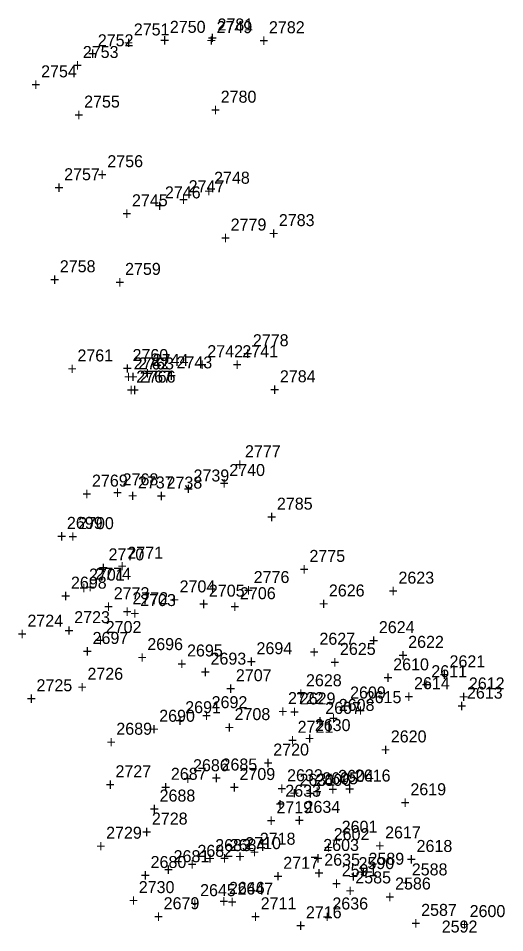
# Model space of a CAD drawing. Extents: x 2192192 to 2193475, y 863716 to 864270.
# Drawn here: x 2192604 to 2192705.3, y 864079.2 to 864269.6 of the extents above; entities that cross this region are included whole.
import ezdxf

# ---------------------------------------------------------------- set-up
doc = ezdxf.new("R2010")
doc.units = 0
for name, color, linetype in [('S_Drainage_Waterway', 7, 'Continuous'), ('S_Ground_Elevation', 7, 'Continuous'), ('S_Ground_SpotElevation', 7, 'Continuous')]:
    doc.layers.add(name, color=color, linetype=linetype)

msp = doc.modelspace()

# ---------------------------------------------------------------- texts
at = {"layer": 'S_Drainage_Waterway'}
for s, p in [('2749', (2192645.32, 864266.53)), ('2752', (2192620.58, 864263.79)), ('+', (2192643.26, 864263.78)), ('+', (2192618.52, 864261.04)), ('2748', (2192644.8, 864235.16)), ('+', (2192642.74, 864232.41)), ('2745', (2192627.7, 864230.46)), ('+', (2192625.64, 864227.71)), ('2741', (2192650.69, 864199.02)), ('2744', (2192632.03, 864197.22)), ('+', (2192648.63, 864196.27)), ('+', (2192629.97, 864194.47)), ('2740', (2192647.97, 864174.28)), ('2737', (2192628.94, 864171.69)), ('+', (2192645.91, 864171.53)), ('+', (2192626.88, 864168.94)), ('2699', (2192614.15, 864163.27)), ('2700', (2192616.48, 864163.21)), ('+', (2192612.08, 864160.52)), ('+', (2192614.42, 864160.46)), ('2698', (2192614.99, 864150.82)), ('2701', (2192618.75, 864152.5)), ('2623', (2192683.2, 864151.86)), ('+', (2192616.69, 864149.75)), ('2626', (2192668.71, 864149.19)), ('+', (2192612.92, 864148.07)), ('2703', (2192629.4, 864147.19)), ('2706', (2192650.2, 864148.62)), ('+', (2192681.14, 864149.11)), ('+', (2192648.14, 864145.87)), ('+', (2192666.65, 864146.44)), ('+', (2192627.33, 864144.44)), ('2702', (2192622.23, 864141.58)), ('2697', (2192619.49, 864139.3)), ('+', (2192620.17, 864138.83)), ('2622', (2192685.23, 864138.49)), ('+', (2192617.43, 864136.55)), ('2694', (2192653.64, 864137.16)), ('2693', (2192644.06, 864134.99)), ('+', (2192651.58, 864134.41)), ('2610', (2192682.11, 864133.8)), ('+', (2192683.17, 864135.74)), ('2621', (2192693.84, 864134.43)), ('+', (2192642, 864132.24)), ('2611', (2192690.05, 864132.37)), ('+', (2192680.05, 864131.05)), ('+', (2192691.78, 864131.68)), ('2612', (2192697.87, 864129.82)), ('2609', (2192673.13, 864127.93)), ('+', (2192687.99, 864129.62)), ('2629', (2192662.65, 864126.69)), ('+', (2192695.81, 864127.07)), ('2692', (2192644.29, 864125.92)), ('+', (2192671.07, 864125.18)), ('+', (2192642.23, 864123.17)), ('+', (2192660.58, 864123.94)), ('2689', (2192624.44, 864120.39)), ('2630', (2192665.78, 864121.15)), ('+', (2192622.38, 864117.64)), ('+', (2192663.72, 864118.4)), ('2685', (2192646.35, 864112.94)), ('+', (2192644.29, 864110.19)), ('2632', (2192660, 864110.7)), ('2631', (2192662.59, 864109.76)), ('2604', (2192670.63, 864110.57)), ('+', (2192657.93, 864107.95)), ('2633', (2192659.63, 864107.48)), ('+', (2192668.57, 864107.82)), ('2688', (2192633.45, 864106.47)), ('+', (2192660.53, 864107.01)), ('+', (2192631.39, 864103.72)), ('+', (2192657.57, 864104.73)), ('2634', (2192663.64, 864104.11)), ('+', (2192661.58, 864101.36)), ('2601', (2192671.38, 864099.98)), ('2684', (2192648.05, 864096.17)), ('+', (2192669.32, 864097.23)), ('2681', (2192636.37, 864093.84)), ('2680', (2192631.58, 864092.63)), ('+', (2192645.99, 864093.42)), ('2635', (2192667.75, 864093.11)), ('2589', (2192676.96, 864093.31)), ('+', (2192634.31, 864091.09)), ('+', (2192665.68, 864090.36)), ('+', (2192674.9, 864090.56)), ('2588', (2192685.98, 864091.09)), ('+', (2192629.51, 864089.88)), ('+', (2192683.91, 864088.34)), ('2647', (2192649.66, 864087.1)), ('2679', (2192634.3, 864084.04)), ('+', (2192647.59, 864084.35)), ('2636', (2192669.44, 864083.99)), ('2587', (2192687.93, 864082.66)), ('+', (2192632.23, 864081.29)), ('+', (2192667.37, 864081.24)), ('+', (2192685.86, 864079.91))]:
    msp.add_text(s, height=2.5, dxfattribs=at).set_placement(p)
at = {"layer": 'S_Ground_Elevation'}
for s, p in [('2781', (2192645.51, 864267.08)), ('2782', (2192656.23, 864266.51)), ('+', (2192643.45, 864264.33)), ('+', (2192654.17, 864263.76)), ('2753', (2192617.46, 864261.35)), ('+', (2192615.39, 864258.6)), ('2754', (2192608.77, 864257.32)), ('+', (2192606.71, 864254.57)), ('2780', (2192646.18, 864252.04)), ('2755', (2192617.73, 864251.02)), ('+', (2192644.12, 864249.29)), ('+', (2192615.67, 864248.27)), ('2756', (2192622.57, 864238.6)), ('2757', (2192613.57, 864235.89)), ('+', (2192620.51, 864235.85)), ('+', (2192611.51, 864233.14)), ('2779', (2192648.26, 864225.41)), ('2783', (2192658.29, 864226.33)), ('+', (2192656.23, 864223.58)), ('+', (2192646.2, 864222.66)), ('2758', (2192612.67, 864216.72)), ('2759', (2192626.26, 864216.17)), ('+', (2192610.61, 864213.97)), ('+', (2192624.2, 864213.42)), ('2778', (2192652.88, 864201.31)), ('2761', (2192616.34, 864198.15)), ('2760', (2192627.81, 864198.23)), ('2762', (2192628.05, 864196.48)), ('2763', (2192629.01, 864196.48)), ('+', (2192650.82, 864198.56)), ('+', (2192614.28, 864195.4)), ('+', (2192625.75, 864195.48)), ('+', (2192625.99, 864193.73)), ('+', (2192626.95, 864193.73)), ('2767', (2192628.6, 864193.74)), ('2766', (2192629.33, 864193.73)), ('2784', (2192658.51, 864193.8)), ('+', (2192626.54, 864190.99)), ('+', (2192627.27, 864190.98)), ('+', (2192656.45, 864191.05)), ('2777', (2192651.24, 864178.19)), ('+', (2192649.18, 864175.44)), ('2769', (2192619.37, 864172.07)), ('2768', (2192625.75, 864172.34)), ('+', (2192617.31, 864169.32)), ('+', (2192623.69, 864169.59)), ('2785', (2192657.89, 864167.27)), ('+', (2192655.83, 864164.52)), ('2770', (2192622.82, 864156.71)), ('2771', (2192626.74, 864157.05)), ('2775', (2192664.66, 864156.39)), ('2774', (2192620.07, 864152.67)), ('+', (2192620.76, 864153.96)), ('+', (2192624.68, 864154.3)), ('+', (2192662.6, 864153.64)), ('2776', (2192653.05, 864151.99)), ('+', (2192618.01, 864149.92)), ('2773', (2192623.9, 864148.62)), ('2772', (2192627.79, 864147.58)), ('+', (2192650.99, 864149.24)), ('+', (2192621.84, 864145.87)), ('2723', (2192615.67, 864143.63)), ('+', (2192625.73, 864144.83)), ('2724', (2192605.92, 864142.9)), ('+', (2192603.86, 864140.15)), ('+', (2192613.61, 864140.88)), ('2726', (2192618.42, 864131.84)), ('2707', (2192649.34, 864131.53)), ('2614', (2192686.45, 864129.88)), ('2725', (2192607.82, 864129.45)), ('+', (2192616.36, 864129.09)), ('+', (2192647.28, 864128.78)), ('2613', (2192697.47, 864127.9)), ('+', (2192605.76, 864126.7)), ('2722', (2192660.2, 864126.78)), ('2615', (2192676.39, 864126.97)), ('+', (2192684.38, 864127.13)), ('+', (2192695.41, 864125.15)), ('2708', (2192649.07, 864123.44)), ('+', (2192658.14, 864124.03)), ('+', (2192674.33, 864124.22)), ('2721', (2192662.2, 864120.79)), ('+', (2192647.01, 864120.69)), ('+', (2192660.14, 864118.04)), ('2720', (2192657.13, 864116.05)), ('+', (2192655.07, 864113.3)), ('2727', (2192624.26, 864111.53)), ('2709', (2192650.09, 864110.96)), ('2616', (2192674.12, 864110.64)), ('+', (2192622.2, 864108.78)), ('+', (2192648.03, 864108.21)), ('+', (2192672.06, 864107.89)), ('2719', (2192657.79, 864104.03)), ('2728', (2192631.85, 864101.68)), ('+', (2192655.73, 864101.28)), ('2729', (2192622.31, 864098.73)), ('+', (2192629.79, 864098.93)), ('2718', (2192654.32, 864097.48)), ('2617', (2192680.42, 864098.8)), ('+', (2192620.25, 864095.98)), ('2710', (2192651.29, 864096.56)), ('+', (2192678.35, 864096.05)), ('2618', (2192686.98, 864095.97)), ('+', (2192652.26, 864094.73)), ('+', (2192649.23, 864093.81)), ('2717', (2192659.21, 864092.46)), ('+', (2192684.92, 864093.22)), ('+', (2192657.15, 864089.71)), ('2730', (2192629.11, 864087.4)), ('+', (2192627.05, 864084.65)), ('2711', (2192654.51, 864084.03)), ('2600', (2192698.03, 864082.41)), ('+', (2192652.45, 864081.28)), ('2716', (2192663.93, 864082.16)), ('+', (2192661.87, 864079.41)), ('2592', (2192692.22, 864079.19)), ('+', (2192695.97, 864079.66))]:
    msp.add_text(s, height=2.5, dxfattribs=at).set_placement(p)
at = {"layer": 'S_Ground_SpotElevation'}
for s, p in [('2751', (2192628.08, 864266.05)), ('2750', (2192635.59, 864266.59)), ('+', (2192633.52, 864263.84)), ('+', (2192626.02, 864263.3)), ('2747', (2192639.51, 864233.39)), ('2746', (2192634.56, 864232.11)), ('+', (2192632.5, 864229.36)), ('+', (2192637.45, 864230.64)), ('2742', (2192643.39, 864199.03)), ('2743', (2192636.98, 864196.7)), ('+', (2192641.33, 864196.28)), ('+', (2192634.92, 864193.95)), ('2739', (2192640.52, 864173.14)), ('2738', (2192634.9, 864171.66)), ('+', (2192638.46, 864170.39)), ('+', (2192632.84, 864168.91)), ('2704', (2192637.62, 864150.04)), ('2705', (2192643.72, 864149.15)), ('+', (2192635.56, 864147.29)), ('+', (2192641.66, 864146.4)), ('2624', (2192679.12, 864141.55)), ('2696', (2192630.89, 864138.02)), ('2627', (2192666.74, 864139.14)), ('+', (2192677.06, 864138.8)), ('2695', (2192639.17, 864136.69)), ('+', (2192664.68, 864136.39)), ('2625', (2192671.02, 864137.02)), ('+', (2192628.83, 864135.27)), ('+', (2192668.96, 864134.27)), ('+', (2192637.11, 864133.94)), ('2628', (2192663.95, 864130.49)), ('+', (2192661.89, 864127.74)), ('2691', (2192638.79, 864124.87)), ('2607', (2192667.96, 864124.73)), ('2608', (2192670.77, 864125.35)), ('2690', (2192633.37, 864123.09)), ('+', (2192636.73, 864122.12)), ('+', (2192665.9, 864121.98)), ('+', (2192668.71, 864122.6)), ('+', (2192631.31, 864120.34)), ('2620', (2192681.61, 864118.79)), ('+', (2192679.55, 864116.04)), ('2686', (2192640.42, 864112.79)), ('2687', (2192635.8, 864111)), ('+', (2192638.36, 864110.04)), ('2606', (2192665.93, 864109.73)), ('2605', (2192667.34, 864110.07)), ('+', (2192633.73, 864108.25)), ('2619', (2192685.69, 864107.78)), ('+', (2192663.87, 864106.98)), ('+', (2192665.28, 864107.32)), ('+', (2192683.62, 864105.03)), ('2602', (2192669.72, 864098.44)), ('2683', (2192645.03, 864096.15)), ('2603', (2192667.54, 864096.18)), ('2682', (2192641.33, 864094.95)), ('+', (2192667.66, 864095.69)), ('+', (2192639.27, 864092.2)), ('+', (2192642.97, 864093.4)), ('+', (2192665.48, 864093.43)), ('2590', (2192674.88, 864092.4)), ('2591', (2192671.39, 864090.92)), ('+', (2192672.82, 864089.65)), ('2585', (2192674.22, 864089.42)), ('2586', (2192682.5, 864088.15)), ('2645', (2192641.89, 864086.77)), ('2646', (2192647.91, 864087.24)), ('+', (2192669.33, 864088.17)), ('+', (2192672.16, 864086.67)), ('+', (2192680.44, 864085.4)), ('+', (2192639.83, 864084.02)), ('+', (2192645.85, 864084.49))]:
    msp.add_text(s, height=2.5, dxfattribs=at).set_placement(p)

doc.saveas('drawing.dxf')
